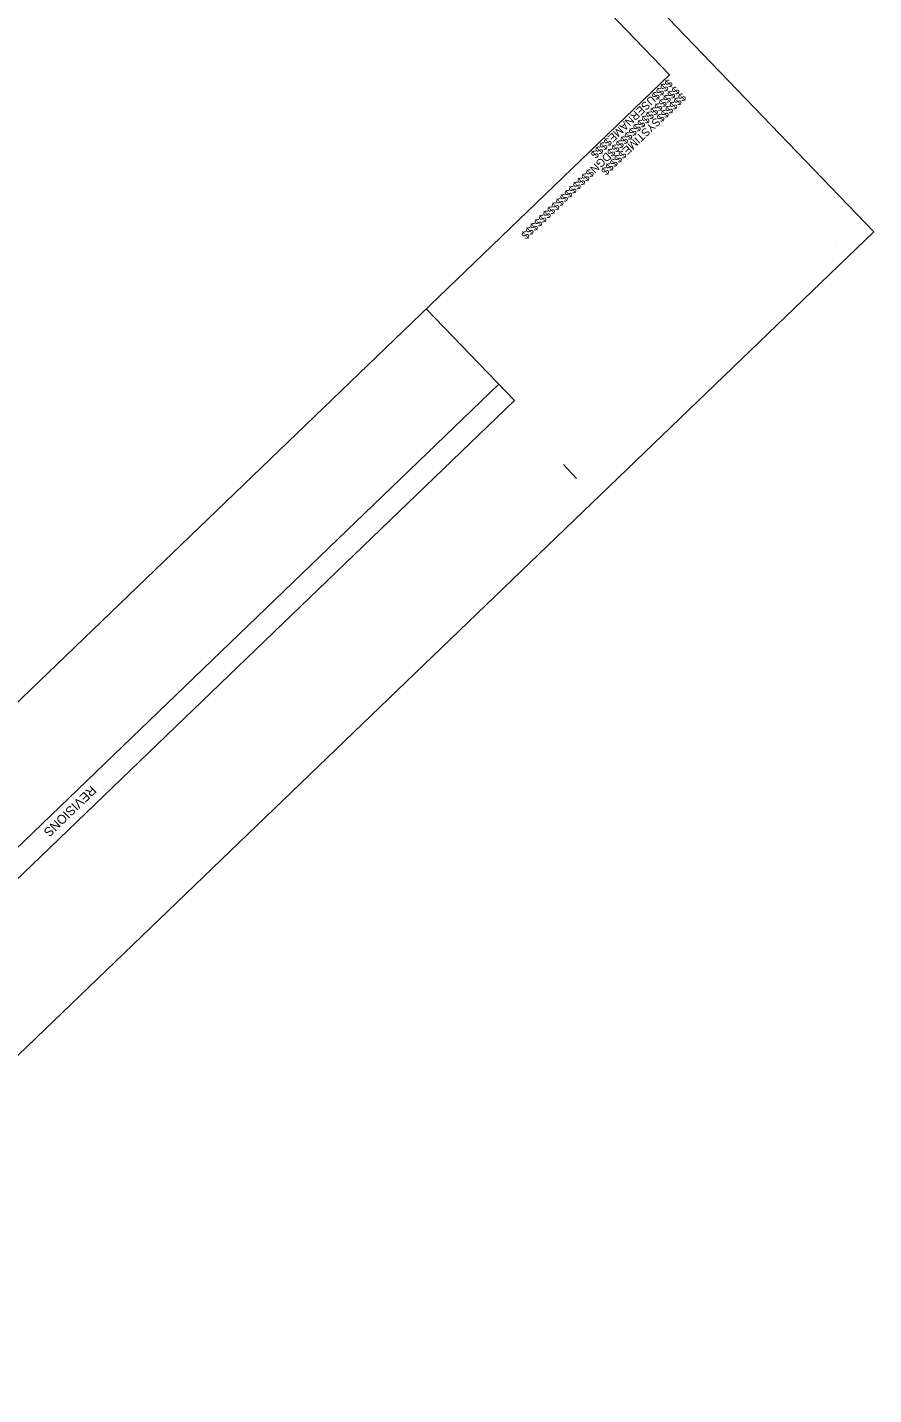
# Model space of a CAD drawing. Extents: x 473158 to 477500, y 500738 to 505114.
# Drawn here: x 476270 to 477500, y 500738 to 502724 of the extents above; entities that cross this region are included whole.
import ezdxf

# ---------------------------------------------------------------- set-up
doc = ezdxf.new("R2010")
doc.units = 0
for name, color, linetype in [('CTL Sheet Border CELL', 7, 'Continuous'), ('Sheet Block Revision CELL', 7, 'Continuous'), ('Sheet Plot Border Outside CELL', 7, 'Continuous')]:
    doc.layers.add(name, color=color, linetype=linetype)

msp = doc.modelspace()

# ---------------------------------------------------------------- linework, layer by layer
at = {"layer": 'CTL Sheet Border CELL'}
for p, q in [((477203.2, 502655), (477203.2, 502655)), ((477203.2, 502655), (477203.2, 502655)), ((477203.2, 502655), (477203.2, 502655)), ((477203.2, 502655), (477203.2, 502655)), ((477203.2, 502655), (477203.2, 502655)), ((477203.2, 502655), (477203.2, 502655)), ((477203.2, 502655), (477203.2, 502655)), ((477203.2, 502655), (477203.2, 502655)), ((477203.2, 502655), (477203.2, 502655)), ((477203.2, 502655), (477203.2, 502655)), ((477203.2, 502655), (477203.2, 502655)), ((477499.6, 502426.8), (477499.6, 502426.8)), ((477443.8, 502413.1), (477443.8, 502413.1)), ((477068.2, 502068.6), (477049, 502088.6))]:
    msp.add_line(p, q, dxfattribs=at)
msp.add_lwpolyline([(473224.2, 503436.3), (475527.6, 501042.6), (477203.2, 502655), (474899.8, 505048.7)], close=True, dxfattribs=at)
msp.add_lwpolyline([(477145.6, 502714.8), (477145.6, 502714.8)], dxfattribs=at)
msp.add_lwpolyline([(477145.6, 502714.8), (477145.6, 502714.8)], dxfattribs=at)
at = {"layer": 'Sheet Block Revision CELL'}
for p, q in [((476849.7, 502314.8), (476978, 502181.6)), ((476955, 502205.5), (475693.6, 500991.7)), ((476978, 502181.6), (475716.7, 500967.7))]:
    msp.add_line(p, q, dxfattribs=at)
at = {"layer": 'Sheet Plot Border Outside CELL'}
msp.add_lwpolyline([(477499.6, 502426.8), (474913.6, 505114.2), (473158.2, 503425.1), (475744.2, 500737.7)], close=True, dxfattribs=at)

# ---------------------------------------------------------------- texts
at = {"layer": 'CTL Sheet Border CELL'}
for s, p in [('$$$$USERNAME$$$$', (477201.1, 502649.6)), ('$$$$$$$$$$$$$$$$DGN$$$$$$$$$$$$$$$$', (477211.2, 502639.2)), ('$$$$$$SYSTIME$$$$$', (477220.5, 502629.5))]:
    msp.add_text(s, height=11.627, rotation=223.8985, dxfattribs=at).set_placement(p)
at = {"layer": 'Sheet Block Revision CELL'}
msp.add_text('REVISIONS', height=13.28, rotation=223.8985, dxfattribs=at).set_placement((476362.8, 501623.5))

doc.saveas('drawing.dxf')
